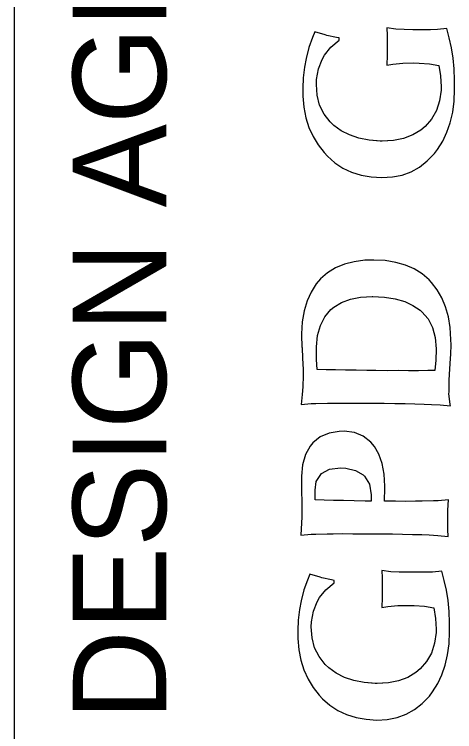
# Model space of a CAD drawing. Extents: x 0 to 34, y 0 to 22.
# Drawn here: x 32.5 to 32.971, y 19.211 to 19.98 of the extents above; entities that cross this region are included whole.
import ezdxf

# ---------------------------------------------------------------- set-up
doc = ezdxf.new("R2010")
doc.units = 0
for name, color, linetype in [('SH_Border', 7, 'Continuous'), ('SH_Data', 7, 'Continuous'), ('SH_Text', 7, 'Continuous')]:
    doc.layers.add(name, color=color, linetype=linetype)

msp = doc.modelspace()

# ---------------------------------------------------------------- linework, layer by layer
at = {"layer": 'SH_Border'}
msp.add_line((32.5, 0.5), (32.5, 21.5), dxfattribs=at)
at = {"layer": 'SH_Text'}
for points in [[(32.87976, 19.84559), (32.86881, 19.84771), (32.85888, 19.85112), (32.84997, 19.85553), (32.84209, 19.86138), (32.83822, 19.86502), (32.83152, 19.87346), (32.82684, 19.88288), (32.82405, 19.89359), (32.82329, 19.90515), (32.82349, 19.91063), (32.82547, 19.92187), (32.82961, 19.93208), (32.8321, 19.93653), (32.83896, 19.94513), (32.84769, 19.95256), (32.84772, 19.95515), (32.84483, 19.95561), (32.83446, 19.95787), (32.83259, 19.95847), (32.82179, 19.9616), (32.81914, 19.95556), (32.81543, 19.94491), (32.81229, 19.93311), (32.81062, 19.92388), (32.80921, 19.91235), (32.80868, 19.90138), (32.80889, 19.89272), (32.80993, 19.88087), (32.81214, 19.86959), (32.81536, 19.85917), (32.81975, 19.84946), (32.82515, 19.84046), (32.83157, 19.83217), (32.83529, 19.82824), (32.84316, 19.82138), (32.85177, 19.81567), (32.86111, 19.81126), (32.87119, 19.80813), (32.882, 19.80616), (32.89339, 19.80548), (32.90466, 19.80609), (32.91507, 19.80816), (32.92492, 19.81168), (32.93391, 19.81665), (32.94206, 19.82321), (32.94964, 19.83108), (32.95314, 19.83567), (32.95857, 19.84443), (32.96313, 19.85405), (32.96669, 19.86427), (32.96924, 19.87536), (32.9708, 19.88733), (32.97135, 19.89988), (32.97129, 19.9097), (32.97083, 19.92183), (32.96964, 19.93353), (32.96801, 19.94452), (32.96565, 19.95508), (32.96286, 19.96521), (32.95289, 19.964), (32.94552, 19.96378), (32.93253, 19.96375), (32.92676, 19.96381), (32.91738, 19.96404), (32.90829, 19.96441), (32.89863, 19.9658), (32.89913, 19.95785), (32.89916, 19.94573), (32.89908, 19.93678), (32.89884, 19.92581), (32.9052, 19.92691), (32.91589, 19.92796), (32.92744, 19.92829), (32.93336, 19.92809), (32.94446, 19.92727), (32.95455, 19.92573), (32.95455, 19.92544), (32.95632, 19.91431), (32.95694, 19.90261), (32.95676, 19.89929), (32.95521, 19.88762), (32.9518, 19.87726), (32.94666, 19.86806), (32.93966, 19.86005), (32.935, 19.85619), (32.92644, 19.85107), (32.91673, 19.84741), (32.90589, 19.8452), (32.89272, 19.84453), (32.87976, 19.84559)], [(32.82179, 19.9616), (32.81914, 19.95556), (32.81543, 19.94491), (32.81229, 19.93311), (32.81062, 19.92388), (32.80921, 19.91235), (32.80868, 19.90138)], [(32.82329, 19.90515), (32.82349, 19.91063), (32.82547, 19.92187), (32.82961, 19.93208), (32.8321, 19.93653), (32.83896, 19.94513), (32.84769, 19.95256), (32.84772, 19.95515), (32.84483, 19.95561), (32.83446, 19.95787), (32.83259, 19.95847), (32.82179, 19.9616)], [(32.82329, 19.90515), (32.82349, 19.91063), (32.82547, 19.92187), (32.82961, 19.93208), (32.8321, 19.93653), (32.83896, 19.94513), (32.84769, 19.95256), (32.84772, 19.95515), (32.84483, 19.95561), (32.83446, 19.95787), (32.83259, 19.95847), (32.82179, 19.9616)], [(32.95857, 19.84443), (32.96313, 19.85405), (32.96669, 19.86427), (32.96924, 19.87536), (32.9708, 19.88733), (32.97135, 19.89988), (32.97129, 19.9097), (32.97083, 19.92183), (32.96964, 19.93353), (32.96801, 19.94452), (32.96565, 19.95508), (32.96286, 19.96521), (32.95289, 19.964), (32.94552, 19.96378), (32.93253, 19.96375), (32.92676, 19.96381), (32.91738, 19.96404), (32.90829, 19.96441), (32.89863, 19.9658)], [(32.89863, 19.9658), (32.89913, 19.95785), (32.89916, 19.94573)], [(32.89916, 19.94573), (32.89908, 19.93678), (32.89884, 19.92581)], [(32.89884, 19.92581), (32.9052, 19.92691)], [(32.9052, 19.92691), (32.91589, 19.92796), (32.92744, 19.92829), (32.93336, 19.92809), (32.94446, 19.92727), (32.95455, 19.92573), (32.95455, 19.92544), (32.95632, 19.91431), (32.95694, 19.90261)], [(32.80868, 19.90138), (32.80889, 19.89272), (32.80993, 19.88087), (32.81214, 19.86959), (32.81536, 19.85917), (32.81975, 19.84946), (32.82515, 19.84046), (32.83157, 19.83217), (32.83529, 19.82824), (32.84316, 19.82138), (32.85177, 19.81567), (32.86111, 19.81126), (32.87119, 19.80813), (32.882, 19.80616), (32.89339, 19.80548), (32.90466, 19.80609), (32.91507, 19.80816), (32.92492, 19.81168), (32.93391, 19.81665), (32.94206, 19.82321), (32.94964, 19.83108), (32.95314, 19.83567), (32.95857, 19.84443)], [(32.95694, 19.90261), (32.95676, 19.89929), (32.95521, 19.88762), (32.9518, 19.87726), (32.94666, 19.86806), (32.93966, 19.86005), (32.935, 19.85619), (32.92644, 19.85107), (32.91673, 19.84741), (32.90589, 19.8452), (32.8939, 19.84459), (32.89173, 19.84461), (32.87976, 19.84559), (32.86881, 19.84771), (32.85888, 19.85112), (32.84997, 19.85553), (32.84209, 19.86138), (32.83822, 19.86502), (32.83152, 19.87346), (32.82684, 19.88288), (32.82405, 19.89359), (32.82329, 19.90515)], [(32.91865, 19.71156), (32.90829, 19.71454), (32.89705, 19.71638), (32.88493, 19.71707), (32.87511, 19.71672), (32.86369, 19.71524), (32.85327, 19.71245), (32.84385, 19.7085), (32.83529, 19.70338), (32.82787, 19.69695), (32.82305, 19.69137), (32.81763, 19.68276), (32.81336, 19.67327), (32.81023, 19.66247), (32.80824, 19.6508), (32.80755, 19.63796), (32.80754, 19.63666), (32.80785, 19.62395), (32.80799, 19.62294), (32.80846, 19.61182), (32.80907, 19.59983), (32.80916, 19.59319), (32.8089, 19.58107), (32.80825, 19.57285), (32.80699, 19.56218), (32.81783, 19.56309), (32.82288, 19.56333), (32.83515, 19.56365), (32.84266, 19.56373), (32.85291, 19.56377), (32.86374, 19.56367), (32.87514, 19.56371), (32.88698, 19.5636), (32.89592, 19.56352), (32.90733, 19.56342), (32.9183, 19.56317), (32.92883, 19.56293), (32.93864, 19.56269), (32.94644, 19.56233), (32.95581, 19.56181), (32.95596, 19.56181), (32.96677, 19.5607), (32.9665, 19.56229), (32.96531, 19.57385), (32.96532, 19.57544), (32.96543, 19.58684), (32.96544, 19.58843), (32.96627, 19.60026), (32.96681, 19.61137), (32.96714, 19.61613), (32.96752, 19.62623), (32.96743, 19.63201), (32.96654, 19.64457), (32.96462, 19.65628), (32.96169, 19.66685), (32.95774, 19.67655), (32.95262, 19.68526), (32.94649, 19.69311), (32.94406, 19.69574), (32.93647, 19.70216), (32.928, 19.70743), (32.91865, 19.71156)], [(32.95262, 19.68526), (32.94649, 19.69311), (32.94406, 19.69574), (32.93647, 19.70216), (32.928, 19.70743), (32.91865, 19.71156), (32.90829, 19.71454), (32.89705, 19.71638), (32.88493, 19.71707), (32.87511, 19.71672), (32.86369, 19.71524), (32.85327, 19.71245), (32.84385, 19.7085), (32.83529, 19.70338), (32.82787, 19.69695), (32.82305, 19.69137)], [(32.82305, 19.69137), (32.81763, 19.68276), (32.81336, 19.67327), (32.81023, 19.66247)], [(32.96462, 19.65628), (32.96169, 19.66685), (32.95774, 19.67655), (32.95262, 19.68526)], [(32.91097, 19.59846), (32.89942, 19.59842), (32.88715, 19.59854), (32.87748, 19.59863), (32.86579, 19.59888), (32.85453, 19.59898), (32.84385, 19.59922), (32.83375, 19.59946), (32.82408, 19.59984), (32.8236, 19.61024), (32.82342, 19.62208), (32.82344, 19.62395), (32.82471, 19.63621), (32.8277, 19.64701), (32.8324, 19.6562), (32.83897, 19.66394), (32.84202, 19.66651), (32.85015, 19.67148), (32.85971, 19.67515), (32.8707, 19.67721), (32.88338, 19.67783), (32.8964, 19.67712), (32.90778, 19.67528), (32.91786, 19.67245), (32.92677, 19.66832), (32.93438, 19.6632), (32.93624, 19.6616), (32.94295, 19.65388), (32.94777, 19.6446), (32.95056, 19.63389), (32.95146, 19.62174), (32.9512, 19.60964), (32.95024, 19.59868), (32.94273, 19.5986), (32.93277, 19.5984), (32.92208, 19.59836), (32.91097, 19.59846)], [(32.82342, 19.62208), (32.82344, 19.62395), (32.82471, 19.63621), (32.8277, 19.64701), (32.8324, 19.6562), (32.83897, 19.66394), (32.84202, 19.66651), (32.85015, 19.67148), (32.85971, 19.67515), (32.8707, 19.67721), (32.88312, 19.67782), (32.8837, 19.67782), (32.8964, 19.67712), (32.90778, 19.67528), (32.91786, 19.67245), (32.92677, 19.66832), (32.93438, 19.6632), (32.93624, 19.6616), (32.94295, 19.65388), (32.94777, 19.6446), (32.95056, 19.63389), (32.95146, 19.62176), (32.95146, 19.62162)], [(32.81023, 19.66247), (32.80824, 19.6508), (32.80755, 19.63796)], [(32.96543, 19.58684), (32.96544, 19.58843), (32.96627, 19.60026), (32.96681, 19.61137), (32.96714, 19.61613), (32.96752, 19.62623), (32.96743, 19.63201), (32.96654, 19.64457), (32.96462, 19.65628)], [(32.96543, 19.58684), (32.96544, 19.58843), (32.96627, 19.60026), (32.96681, 19.61137), (32.96714, 19.61613), (32.96752, 19.62623), (32.96743, 19.63201), (32.96654, 19.64457), (32.96462, 19.65628)], [(32.80755, 19.63796), (32.80754, 19.63666), (32.80785, 19.62395), (32.80799, 19.62294), (32.80846, 19.61182), (32.80907, 19.59983), (32.80916, 19.59319)], [(32.95146, 19.62162), (32.9512, 19.60964), (32.95024, 19.59868), (32.94273, 19.5986), (32.93277, 19.5984), (32.92208, 19.59836), (32.91097, 19.59846), (32.89942, 19.59842), (32.88715, 19.59854), (32.87748, 19.59863), (32.86579, 19.59888), (32.85453, 19.59898), (32.84385, 19.59922), (32.83375, 19.59946), (32.82408, 19.59984), (32.8236, 19.61024), (32.82342, 19.62208)], [(32.80916, 19.59319), (32.8089, 19.58107), (32.80825, 19.57285), (32.80699, 19.56218)], [(32.80699, 19.56218), (32.81783, 19.56309), (32.82288, 19.56333), (32.83515, 19.56365), (32.84266, 19.56373), (32.85291, 19.56377), (32.86374, 19.56367), (32.87514, 19.56371), (32.88698, 19.5636), (32.89592, 19.56352), (32.90733, 19.56342), (32.9183, 19.56317), (32.92883, 19.56293), (32.93864, 19.56269), (32.94644, 19.56233), (32.95581, 19.56181), (32.95596, 19.56181), (32.96677, 19.5607), (32.9665, 19.56229), (32.96531, 19.57385), (32.96532, 19.57544), (32.96543, 19.58684)], [(32.91906, 19.45837), (32.90795, 19.45847), (32.89625, 19.45858), (32.89667, 19.47272), (32.89669, 19.47474), (32.89595, 19.48759), (32.89374, 19.49887), (32.89022, 19.50887), (32.88539, 19.51728), (32.88154, 19.52179), (32.87351, 19.52822), (32.86402, 19.53206), (32.85292, 19.53346), (32.84787, 19.53336), (32.83688, 19.53144), (32.82746, 19.52735), (32.8196, 19.52092), (32.81668, 19.51748), (32.81155, 19.50844), (32.80856, 19.49764), (32.80744, 19.48538), (32.80761, 19.44178), (32.80686, 19.42216), (32.81769, 19.42307), (32.82274, 19.42331), (32.83502, 19.42363), (32.84137, 19.42372), (32.85162, 19.42377), (32.86244, 19.42367), (32.87385, 19.42371), (32.88568, 19.4236), (32.89333, 19.42353), (32.90474, 19.42342), (32.9157, 19.42318), (32.92624, 19.42293), (32.9362, 19.4227), (32.94399, 19.42234), (32.95351, 19.42182), (32.96433, 19.42071), (32.96411, 19.42836), (32.96408, 19.44049), (32.96415, 19.449), (32.96469, 19.45997), (32.95385, 19.45906), (32.9488, 19.45896), (32.93653, 19.45849), (32.9296, 19.45841), (32.91906, 19.45837)], [(32.88539, 19.51728), (32.88154, 19.52179), (32.87351, 19.52822), (32.86402, 19.53206), (32.85292, 19.53346), (32.84787, 19.53336), (32.83688, 19.53144), (32.82746, 19.52735), (32.8196, 19.52092)], [(32.8196, 19.52092), (32.81668, 19.51748), (32.81155, 19.50844), (32.80856, 19.49764)], [(32.89595, 19.48759), (32.89374, 19.49887), (32.89022, 19.50887), (32.88539, 19.51728)], [(32.80856, 19.49764), (32.80744, 19.48538)], [(32.88211, 19.45856), (32.87561, 19.45862), (32.86378, 19.45888), (32.85252, 19.45913), (32.84184, 19.45937), (32.8316, 19.45961), (32.82193, 19.45984), (32.82188, 19.47052), (32.82326, 19.4796), (32.82897, 19.48821), (32.83753, 19.4929), (32.84909, 19.49438), (32.85472, 19.49404), (32.86538, 19.49149), (32.87356, 19.48665), (32.87485, 19.48548), (32.88026, 19.47677), (32.88203, 19.4652), (32.88211, 19.45856)], [(32.82188, 19.47052), (32.82326, 19.4796), (32.82897, 19.48821), (32.83753, 19.4929), (32.84909, 19.49438), (32.85472, 19.49404), (32.86538, 19.49149), (32.87356, 19.48665), (32.87485, 19.48548), (32.88026, 19.47677), (32.88203, 19.4652), (32.88211, 19.45856)], [(32.80744, 19.48538), (32.80761, 19.44178)], [(32.89625, 19.45858), (32.89667, 19.47272), (32.89669, 19.47474), (32.89595, 19.48759)], [(32.89625, 19.45858), (32.89667, 19.47272), (32.89669, 19.47474), (32.89595, 19.48759)], [(32.88211, 19.45856), (32.87561, 19.45862), (32.86378, 19.45888), (32.85252, 19.45913), (32.84184, 19.45937), (32.8316, 19.45961), (32.82193, 19.45984), (32.82188, 19.47052)], [(32.96408, 19.44049), (32.96415, 19.449), (32.96469, 19.45997), (32.96469, 19.45997), (32.95385, 19.45906), (32.9488, 19.45896), (32.93653, 19.45849), (32.9296, 19.45841), (32.91906, 19.45837), (32.90795, 19.45847), (32.89625, 19.45858)], [(32.80761, 19.44178), (32.80686, 19.42216)], [(32.95351, 19.42182), (32.96433, 19.42071), (32.96411, 19.42836), (32.96408, 19.44049)], [(32.80686, 19.42216), (32.81769, 19.42307), (32.82274, 19.42331), (32.83502, 19.42363), (32.84137, 19.42372), (32.85162, 19.42377), (32.86244, 19.42367), (32.87385, 19.42371), (32.88568, 19.4236), (32.89333, 19.42353), (32.90474, 19.42342), (32.9157, 19.42318), (32.92624, 19.42293), (32.9362, 19.4227), (32.94399, 19.42234), (32.95351, 19.42182), (32.95351, 19.42182)], [(32.85352, 19.26959), (32.84461, 19.27414), (32.83672, 19.27984), (32.83286, 19.28363), (32.82615, 19.29207), (32.82148, 19.30149), (32.81869, 19.31206), (32.81793, 19.32376), (32.81812, 19.32924), (32.8201, 19.34048), (32.82424, 19.35055), (32.82673, 19.35514), (32.8336, 19.3636), (32.84233, 19.37102), (32.84235, 19.37362), (32.83947, 19.37422), (32.8291, 19.37648), (32.82723, 19.37708), (32.81643, 19.38021), (32.81377, 19.37403), (32.81007, 19.36338), (32.80693, 19.35157), (32.80525, 19.34249), (32.80385, 19.33096), (32.80331, 19.31985), (32.80352, 19.31133), (32.80457, 19.29934), (32.80677, 19.2882), (32.81, 19.27764), (32.81438, 19.26793), (32.81978, 19.25893), (32.8262, 19.25078), (32.82992, 19.24685), (32.8378, 19.23999), (32.8464, 19.23429), (32.85575, 19.22987), (32.86582, 19.22674), (32.87663, 19.22477), (32.88803, 19.22394), (32.89929, 19.22456), (32.9097, 19.22663), (32.91955, 19.23029), (32.92855, 19.23526), (32.93669, 19.24168), (32.94427, 19.24969), (32.94778, 19.25428), (32.9532, 19.26304), (32.95776, 19.27252), (32.96132, 19.28288), (32.96388, 19.29397), (32.96543, 19.30579), (32.96598, 19.31849), (32.96593, 19.32816), (32.96546, 19.34044), (32.96427, 19.352), (32.96264, 19.36313), (32.96028, 19.37369), (32.95749, 19.38367), (32.94752, 19.38247), (32.94016, 19.38239), (32.92716, 19.38236), (32.92139, 19.38242), (32.91201, 19.3825), (32.90292, 19.38288), (32.89326, 19.38427), (32.89376, 19.37647), (32.8938, 19.36434), (32.89371, 19.35539), (32.89347, 19.34442), (32.89983, 19.34552), (32.91052, 19.34657), (32.92207, 19.3469), (32.92799, 19.3467), (32.9391, 19.34588), (32.94919, 19.3442), (32.94918, 19.34405), (32.95096, 19.33278), (32.95157, 19.32122), (32.9514, 19.31776), (32.94985, 19.30623), (32.94643, 19.29572), (32.94129, 19.28667), (32.93429, 19.27866), (32.92964, 19.2748), (32.92107, 19.26968), (32.91137, 19.26602), (32.90052, 19.26381), (32.88735, 19.26314), (32.8744, 19.2642), (32.86345, 19.26632), (32.85352, 19.26959)], [(32.9532, 19.26304), (32.95776, 19.27252), (32.96132, 19.28288), (32.96388, 19.29397), (32.96543, 19.30579), (32.96598, 19.31849), (32.96593, 19.32816), (32.96546, 19.34044), (32.96427, 19.352), (32.96264, 19.36313), (32.96028, 19.37369), (32.95749, 19.38367), (32.94752, 19.38247), (32.94016, 19.38239), (32.92716, 19.38236), (32.92139, 19.38242), (32.91201, 19.3825), (32.90292, 19.38288), (32.89326, 19.38427)], [(32.89326, 19.38427), (32.89376, 19.37647), (32.8938, 19.36434)], [(32.81643, 19.38021), (32.81377, 19.37403), (32.81007, 19.36338), (32.80693, 19.35157), (32.80525, 19.34249), (32.80385, 19.33096), (32.80331, 19.31985)], [(32.81793, 19.32376), (32.81812, 19.32924), (32.8201, 19.34048), (32.82424, 19.35055), (32.82673, 19.35514), (32.8336, 19.3636), (32.84233, 19.37102), (32.84235, 19.37362), (32.83947, 19.37422), (32.8291, 19.37648), (32.82723, 19.37708), (32.81643, 19.38021)], [(32.81793, 19.32376), (32.81812, 19.32924), (32.8201, 19.34048), (32.82424, 19.35055), (32.82673, 19.35514), (32.8336, 19.3636), (32.84233, 19.37102), (32.84235, 19.37362), (32.83947, 19.37422), (32.8291, 19.37648), (32.82723, 19.37708), (32.81643, 19.38021)], [(32.8938, 19.36434), (32.89371, 19.35539), (32.89347, 19.34442)], [(32.89347, 19.34442), (32.89983, 19.34552)], [(32.89983, 19.34552), (32.91052, 19.34657), (32.92207, 19.3469), (32.92799, 19.3467), (32.9391, 19.34588), (32.94919, 19.3442), (32.94918, 19.34405), (32.95096, 19.33278), (32.95157, 19.32122)], [(32.95157, 19.32122), (32.9514, 19.31776), (32.94985, 19.30623), (32.94643, 19.29572), (32.94129, 19.28667), (32.93429, 19.27866), (32.92964, 19.2748), (32.92107, 19.26968), (32.91137, 19.26602), (32.90052, 19.26381), (32.88853, 19.2632), (32.88637, 19.26322), (32.8744, 19.2642), (32.86345, 19.26632), (32.85352, 19.26959), (32.84461, 19.27414), (32.83672, 19.27984), (32.83286, 19.28363), (32.82615, 19.29207), (32.82148, 19.30149), (32.81869, 19.31206), (32.81793, 19.32376)], [(32.80331, 19.31985), (32.80352, 19.31133), (32.80457, 19.29934), (32.80677, 19.2882), (32.81, 19.27764), (32.81438, 19.26793), (32.81978, 19.25893), (32.8262, 19.25078), (32.82992, 19.24685), (32.8378, 19.23999), (32.8464, 19.23429), (32.85575, 19.22987), (32.86582, 19.22674), (32.87663, 19.22477), (32.88803, 19.22394), (32.89929, 19.22456), (32.9097, 19.22663), (32.91955, 19.23029), (32.92855, 19.23526), (32.93669, 19.24168), (32.94427, 19.24969), (32.94778, 19.25428), (32.9532, 19.26304)]]:
    msp.add_lwpolyline(points, dxfattribs=at)

# ---------------------------------------------------------------- texts
at = {"layer": 'SH_Data'}
msp.add_text('DESIGN AGENCY', height=0.1, rotation=90, dxfattribs=at).set_placement((32.66252, 19.2237))

doc.saveas('drawing.dxf')
